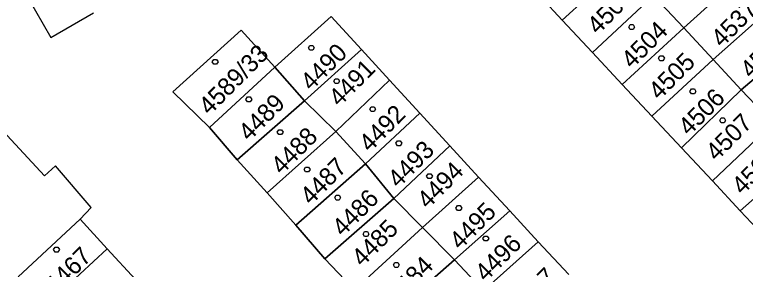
# Model space of a CAD drawing. Extents: x -263587 to -261993, y -1238795 to -1236748.
# Drawn here: x -262984.89 to -262939.57, y -1237544.16 to -1237528.36 of the extents above; entities that cross this region are included whole.
import ezdxf

# ---------------------------------------------------------------- set-up
doc = ezdxf.new("R2010")
doc.units = 0
doc.layers.add('Vrstva 1', color=7, linetype='Continuous')

msp = doc.modelspace()

# ---------------------------------------------------------------- linework, layer by layer
at = {"layer": 'Vrstva 1'}
for p, q in [((-262950.93, -1237528.7), (-262947.12, -1237525.22)), ((-262947.12, -1237525.22), (-262950.93, -1237528.7)), ((-262985.05, -1237525.58), (-262982.64, -1237529.77)), ((-262943.4, -1237529.19), (-262939.64, -1237525.79)), ((-262939.64, -1237525.79), (-262943.4, -1237529.19)), ((-262950.93, -1237528.7), (-262952.82, -1237526.67)), ((-262952.82, -1237526.67), (-262950.93, -1237528.7)), ((-262949.05, -1237530.72), (-262945.28, -1237527.18)), ((-262945.28, -1237527.18), (-262949.05, -1237530.72)), ((-262943.4, -1237529.19), (-262945.28, -1237527.18)), ((-262945.28, -1237527.18), (-262943.4, -1237529.19)), ((-262941.58, -1237531.14), (-262937.77, -1237527.76)), ((-262937.77, -1237527.76), (-262941.58, -1237531.14)), ((-262982.64, -1237529.77), (-262980, -1237528.24)), ((-262968.76, -1237531.62), (-262965.26, -1237528.48)), ((-262965.26, -1237528.48), (-262968.76, -1237531.62)), ((-262965.26, -1237528.48), (-262963.38, -1237530.53)), ((-262963.38, -1237530.53), (-262965.26, -1237528.48)), ((-262949.05, -1237530.72), (-262950.93, -1237528.7)), ((-262950.93, -1237528.7), (-262949.05, -1237530.72)), ((-262975.08, -1237533.15), (-262970.84, -1237529.33)), ((-262970.84, -1237529.33), (-262975.08, -1237533.15)), ((-262970.84, -1237529.33), (-262968.76, -1237531.62)), ((-262968.76, -1237531.62), (-262970.84, -1237529.33)), ((-262947.21, -1237532.69), (-262943.4, -1237529.19)), ((-262943.4, -1237529.19), (-262947.21, -1237532.69)), ((-262941.58, -1237531.14), (-262943.4, -1237529.19)), ((-262943.4, -1237529.19), (-262941.58, -1237531.14)), ((-262939.83, -1237533.02), (-262935.93, -1237529.71)), ((-262935.93, -1237529.71), (-262939.83, -1237533.02)), ((-262966.91, -1237533.7), (-262963.38, -1237530.53)), ((-262963.38, -1237530.53), (-262966.91, -1237533.7)), ((-262963.38, -1237530.53), (-262961.64, -1237532.43)), ((-262961.64, -1237532.43), (-262963.38, -1237530.53)), ((-262947.21, -1237532.69), (-262949.05, -1237530.72)), ((-262949.05, -1237530.72), (-262947.21, -1237532.69)), ((-262945.37, -1237534.66), (-262941.58, -1237531.14)), ((-262941.58, -1237531.14), (-262945.37, -1237534.66)), ((-262939.83, -1237533.02), (-262941.58, -1237531.14)), ((-262941.58, -1237531.14), (-262939.83, -1237533.02)), ((-262972.81, -1237535.36), (-262968.76, -1237531.62)), ((-262968.76, -1237531.62), (-262972.81, -1237535.36)), ((-262966.91, -1237533.7), (-262968.76, -1237531.62)), ((-262968.76, -1237531.62), (-262966.91, -1237533.7)), ((-262964.96, -1237535.62), (-262961.64, -1237532.43)), ((-262961.64, -1237532.43), (-262964.96, -1237535.62)), ((-262961.64, -1237532.43), (-262959.77, -1237534.47)), ((-262959.77, -1237534.47), (-262961.64, -1237532.43)), ((-262945.37, -1237534.66), (-262947.21, -1237532.69)), ((-262947.21, -1237532.69), (-262945.37, -1237534.66)), ((-262972.81, -1237535.36), (-262975.08, -1237533.15)), ((-262975.08, -1237533.15), (-262972.81, -1237535.36)), ((-262943.54, -1237536.62), (-262939.83, -1237533.02)), ((-262939.83, -1237533.02), (-262943.54, -1237536.62)), ((-262937.87, -1237535.11), (-262939.83, -1237533.02)), ((-262939.83, -1237533.02), (-262937.87, -1237535.11)), ((-262971.08, -1237537.36), (-262966.91, -1237533.7)), ((-262966.91, -1237533.7), (-262971.08, -1237537.36)), ((-262964.96, -1237535.62), (-262966.91, -1237533.7)), ((-262966.91, -1237533.7), (-262964.96, -1237535.62)), ((-262963.12, -1237537.62), (-262959.77, -1237534.47)), ((-262959.77, -1237534.47), (-262963.12, -1237537.62)), ((-262959.77, -1237534.47), (-262957.91, -1237536.5)), ((-262957.91, -1237536.5), (-262959.77, -1237534.47)), ((-262943.54, -1237536.62), (-262945.37, -1237534.66)), ((-262945.37, -1237534.66), (-262943.54, -1237536.62)), ((-262941.62, -1237538.68), (-262937.87, -1237535.11)), ((-262937.87, -1237535.11), (-262941.62, -1237538.68)), ((-262983.03, -1237538.36), (-262985.62, -1237535.56)), ((-262971.08, -1237537.36), (-262972.81, -1237535.36)), ((-262972.81, -1237535.36), (-262971.08, -1237537.36)), ((-262969.23, -1237539.42), (-262964.96, -1237535.62)), ((-262964.96, -1237535.62), (-262969.23, -1237539.42)), ((-262963.12, -1237537.62), (-262964.96, -1237535.62)), ((-262964.96, -1237535.62), (-262963.12, -1237537.62)), ((-262961.37, -1237539.76), (-262957.91, -1237536.5)), ((-262957.91, -1237536.5), (-262961.37, -1237539.76)), ((-262957.91, -1237536.5), (-262956.13, -1237538.44)), ((-262956.13, -1237538.44), (-262957.91, -1237536.5)), ((-262941.62, -1237538.68), (-262943.54, -1237536.62)), ((-262943.54, -1237536.62), (-262941.62, -1237538.68)), ((-262969.23, -1237539.42), (-262971.08, -1237537.36)), ((-262971.08, -1237537.36), (-262969.23, -1237539.42)), ((-262939.89, -1237540.53), (-262936.03, -1237537.08)), ((-262936.03, -1237537.08), (-262939.89, -1237540.53)), ((-262982.35, -1237537.75), (-262983.03, -1237538.36)), ((-262980.13, -1237540.32), (-262982.35, -1237537.75)), ((-262967.45, -1237541.43), (-262963.12, -1237537.62)), ((-262963.12, -1237537.62), (-262967.45, -1237541.43)), ((-262961.37, -1237539.76), (-262963.12, -1237537.62)), ((-262963.12, -1237537.62), (-262961.37, -1237539.76)), ((-262959.6, -1237541.57), (-262956.13, -1237538.44)), ((-262956.13, -1237538.44), (-262959.6, -1237541.57)), ((-262956.13, -1237538.44), (-262954.19, -1237540.53)), ((-262954.19, -1237540.53), (-262956.13, -1237538.44)), ((-262939.89, -1237540.53), (-262941.62, -1237538.68)), ((-262941.62, -1237538.68), (-262939.89, -1237540.53)), ((-262967.45, -1237541.43), (-262969.23, -1237539.42)), ((-262969.23, -1237539.42), (-262967.45, -1237541.43)), ((-262965.65, -1237543.51), (-262961.37, -1237539.76)), ((-262961.37, -1237539.76), (-262965.65, -1237543.51)), ((-262959.6, -1237541.57), (-262961.37, -1237539.76)), ((-262961.37, -1237539.76), (-262959.6, -1237541.57)), ((-262980.83, -1237541.04), (-262980.13, -1237540.32)), ((-262957.61, -1237543.57), (-262954.19, -1237540.53)), ((-262954.19, -1237540.53), (-262957.61, -1237543.57)), ((-262954.19, -1237540.53), (-262952.42, -1237542.45)), ((-262952.42, -1237542.45), (-262954.19, -1237540.53)), ((-262938.03, -1237542.52), (-262939.89, -1237540.53)), ((-262939.89, -1237540.53), (-262938.03, -1237542.52)), ((-262984.67, -1237544.63), (-262980.83, -1237541.04)), ((-262980.83, -1237541.04), (-262979.14, -1237542.88)), ((-262979.14, -1237542.88), (-262980.83, -1237541.04)), ((-262965.65, -1237543.51), (-262967.45, -1237541.43)), ((-262967.45, -1237541.43), (-262965.65, -1237543.51)), ((-262963.81, -1237545.43), (-262959.6, -1237541.57)), ((-262959.6, -1237541.57), (-262963.81, -1237545.43)), ((-262957.61, -1237543.57), (-262959.6, -1237541.57)), ((-262959.6, -1237541.57), (-262957.61, -1237543.57)), ((-262955.81, -1237545.48), (-262952.42, -1237542.45)), ((-262952.42, -1237542.45), (-262955.81, -1237545.48)), ((-262952.42, -1237542.45), (-262950.53, -1237544.48)), ((-262950.53, -1237544.48), (-262952.42, -1237542.45)), ((-262983.03, -1237546.48), (-262979.14, -1237542.88)), ((-262979.14, -1237542.88), (-262983.03, -1237546.48)), ((-262979.14, -1237542.88), (-262977.38, -1237544.8)), ((-262977.38, -1237544.8), (-262979.14, -1237542.88)), ((-262963.81, -1237545.43), (-262965.65, -1237543.51)), ((-262965.65, -1237543.51), (-262963.81, -1237545.43)), ((-262961.97, -1237547.39), (-262957.61, -1237543.57)), ((-262957.61, -1237543.57), (-262961.97, -1237547.39)), ((-262955.81, -1237545.48), (-262957.61, -1237543.57)), ((-262957.61, -1237543.57), (-262955.81, -1237545.48))]:
    msp.add_line(p, q, dxfattribs=at)
for points in [[(-262946.54, -1237528.98), (-262946.45, -1237529.13), (-262946.54, -1237529.28), (-262946.72, -1237529.28), (-262946.81, -1237529.13), (-262946.72, -1237528.98)], [(-262966.4, -1237530.27), (-262966.31, -1237530.42), (-262966.4, -1237530.57), (-262966.58, -1237530.57), (-262966.67, -1237530.42), (-262966.58, -1237530.27)], [(-262972.36, -1237531.14), (-262972.27, -1237531.29), (-262972.36, -1237531.44), (-262972.54, -1237531.44), (-262972.63, -1237531.29), (-262972.54, -1237531.14)], [(-262944.69, -1237530.92), (-262944.6, -1237531.07), (-262944.69, -1237531.22), (-262944.87, -1237531.22), (-262944.96, -1237531.07), (-262944.87, -1237530.92)], [(-262964.83, -1237532.34), (-262964.74, -1237532.49), (-262964.83, -1237532.64), (-262965.01, -1237532.64), (-262965.1, -1237532.49), (-262965.01, -1237532.34)], [(-262942.74, -1237532.97), (-262942.65, -1237533.12), (-262942.74, -1237533.27), (-262942.92, -1237533.27), (-262943.01, -1237533.12), (-262942.92, -1237532.97)], [(-262970.27, -1237533.47), (-262970.18, -1237533.62), (-262970.27, -1237533.77), (-262970.45, -1237533.77), (-262970.54, -1237533.62), (-262970.45, -1237533.47)], [(-262962.59, -1237534.08), (-262962.5, -1237534.23), (-262962.59, -1237534.38), (-262962.77, -1237534.38), (-262962.86, -1237534.23), (-262962.77, -1237534.08)], [(-262940.89, -1237534.77), (-262940.8, -1237534.92), (-262940.89, -1237535.07), (-262941.07, -1237535.07), (-262941.16, -1237534.92), (-262941.07, -1237534.77)], [(-262968.33, -1237535.5), (-262968.24, -1237535.65), (-262968.33, -1237535.8), (-262968.51, -1237535.8), (-262968.6, -1237535.65), (-262968.51, -1237535.5)], [(-262960.97, -1237536.19), (-262960.88, -1237536.34), (-262960.97, -1237536.49), (-262961.15, -1237536.49), (-262961.24, -1237536.34), (-262961.15, -1237536.19)], [(-262966.66, -1237537.82), (-262966.57, -1237537.97), (-262966.66, -1237538.12), (-262966.84, -1237538.12), (-262966.93, -1237537.97), (-262966.84, -1237537.82)], [(-262959.07, -1237538.23), (-262958.98, -1237538.38), (-262959.07, -1237538.53), (-262959.25, -1237538.53), (-262959.34, -1237538.38), (-262959.25, -1237538.23)], [(-262964.76, -1237539.56), (-262964.67, -1237539.71), (-262964.76, -1237539.86), (-262964.94, -1237539.86), (-262965.03, -1237539.71), (-262964.94, -1237539.56)], [(-262957.25, -1237540.21), (-262957.16, -1237540.36), (-262957.25, -1237540.51), (-262957.43, -1237540.51), (-262957.52, -1237540.36), (-262957.43, -1237540.21)], [(-262963.01, -1237541.82), (-262962.92, -1237541.97), (-262963.01, -1237542.12), (-262963.19, -1237542.12), (-262963.28, -1237541.97), (-262963.19, -1237541.82)], [(-262955.58, -1237542.1), (-262955.49, -1237542.25), (-262955.58, -1237542.4), (-262955.76, -1237542.4), (-262955.85, -1237542.25), (-262955.76, -1237542.1)], [(-262982.2, -1237542.79), (-262982.11, -1237542.94), (-262982.2, -1237543.09), (-262982.38, -1237543.09), (-262982.47, -1237542.94), (-262982.38, -1237542.79)], [(-262961.13, -1237543.74), (-262961.04, -1237543.89), (-262961.13, -1237544.04), (-262961.31, -1237544.04), (-262961.4, -1237543.89), (-262961.31, -1237543.74)]]:
    msp.add_lwpolyline(points, close=True, dxfattribs=at)

# ---------------------------------------------------------------- texts
for s, p in [('4503', (-262948.73, -1237529.65)), ('4537', (-262941.037, -1237530.446)), ('4504', (-262946.61, -1237531.77)), ('4536', (-262939.228, -1237532.378)), ('4589/33', (-262972.809, -1237534.652)), ('4490', (-262966.493, -1237533.143)), ('4505', (-262944.92, -1237533.71)), ('4491', (-262964.748, -1237534.127)), ('4506', (-262943.072, -1237535.932)), ('4489', (-262970.35, -1237536.269)), ('4492', (-262962.87, -1237536.949)), ('4507', (-262941.37, -1237537.5)), ('4488', (-262968.327, -1237538.336)), ('4493', (-262961.09, -1237539.169)), ('4508', (-262939.76, -1237539.59)), ('4487', (-262966.517, -1237540.226)), ('4494', (-262959.27, -1237540.469)), ('4486', (-262964.538, -1237542.178)), ('4495', (-262957.26, -1237542.999)), ('4485', (-262963.327, -1237544.056)), ('4496', (-262955.681, -1237544.981)), ('4467', (-262982.338, -1237545.768)), ('4484', (-262961.147, -1237546.336)), ('4497', (-262953.54, -1237547.049))]:
    msp.add_text(s, height=1.1, rotation=45.0918, dxfattribs=at).set_placement(p)

doc.saveas('drawing.dxf')
